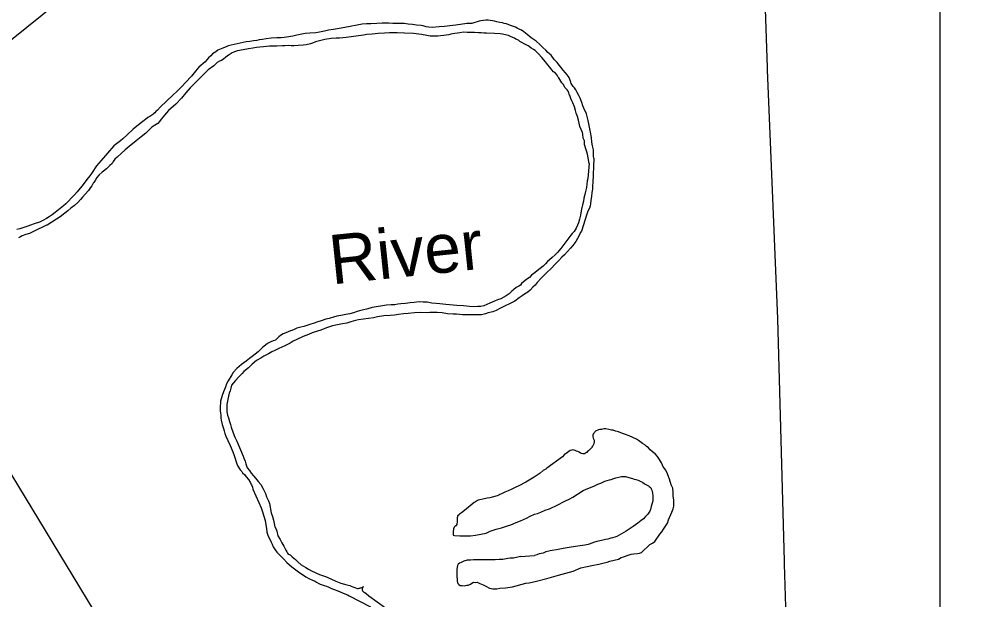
# Model space of a CAD drawing. Extents: x 1720274 to 1751788, y 372074 to 391887.
# Drawn here: x 1725183 to 1726800, y 387969 to 388953 of the extents above; entities that cross this region are included whole.
import ezdxf

# ---------------------------------------------------------------- set-up
doc = ezdxf.new("R2010")
doc.units = 0
for name, color, linetype in [('Level 10', 7, 'Continuous'), ('Level 2', 7, 'Continuous'), ('Level 9', 7, 'Continuous'), ('R_Draft', 7, 'Continuous')]:
    doc.layers.add(name, color=color, linetype=linetype)

msp = doc.modelspace()

# ---------------------------------------------------------------- linework, layer by layer
at = {"layer": 'Level 10'}
msp.add_lwpolyline([(1725245.1, 388978.7), (1725004.5, 388785.1)], dxfattribs=at)
at = {"layer": 'Level 2'}
msp.add_lwpolyline([(1726517.5, 386794.1), (1726507.7, 387180.9), (1726508, 387187.3), (1726491.7, 387614.2), (1726479.2, 388029.9), (1726479.1, 388035), (1726467.4, 388445.5), (1726450.4, 388867), (1726450.4, 388871.1), (1726443.9, 389052.9)], dxfattribs=at)
at = {"layer": 'Level 9'}
for points in [[(1726156, 388717.6), (1726155.7, 388721.1), (1726155.8, 388726.7), (1726155.5, 388731.7), (1726153.9, 388738.3), (1726152.7, 388744.8), (1726152, 388752.4), (1726150.4, 388761.5), (1726147.6, 388775.5), (1726146.3, 388781.5), (1726143.5, 388792.8), (1726139.3, 388802.4), (1726137.4, 388806.3), (1726135.8, 388811.9), (1726132.9, 388819.3), (1726130.7, 388823.6), (1726128, 388828.9), (1726125.5, 388833.1), (1726123.3, 388836.6), (1726121.2, 388839), (1726117.5, 388844.1), (1726117, 388846.3), (1726115, 388852.3), (1726114.2, 388854.3), (1726111, 388859), (1726108.1, 388862.4), (1726104.3, 388866.4), (1726094.1, 388879.4), (1726089.2, 388884.9), (1726083.6, 388892), (1726078.4, 388896.7), (1726075.1, 388900.3), (1726069.9, 388905.3), (1726064.7, 388910.1), (1726058.3, 388915.6), (1726050.1, 388921.5), (1726043.3, 388927.3), (1726037.4, 388931.7), (1726033.9, 388934.3), (1726029.7, 388936.2), (1726026.2, 388938), (1726023.3, 388939.3), (1726020.1, 388940.7), (1726016.7, 388942), (1726012.1, 388943.3), (1726008.3, 388944.9), (1726004.4, 388946), (1726001.3, 388946.7), (1725996.8, 388947.5), (1725991.6, 388948.8), (1725987.8, 388949.6), (1725984.3, 388950.3), (1725980.8, 388950.8), (1725977.1, 388951.1), (1725973.2, 388951.5), (1725969.2, 388950.9), (1725965, 388950.4), (1725961.9, 388949.7), (1725958.6, 388948.8), (1725954.4, 388947.4), (1725949.8, 388945.8), (1725946.5, 388945.7), (1725940.9, 388945.5), (1725930.3, 388944.2), (1725926.1, 388943.6), (1725922.5, 388942.9), (1725917.6, 388942.2), (1725912.4, 388941.6), (1725903.1, 388940.8), (1725894.2, 388940), (1725882.2, 388938.9), (1725877, 388939.3), (1725872.2, 388940), (1725867, 388941.5), (1725863.8, 388942.1), (1725855.6, 388942.8), (1725849.1, 388944), (1725841.9, 388944.7), (1725835.1, 388945.9), (1725816, 388945.7), (1725809.1, 388946.2), (1725803.2, 388946.3), (1725797.9, 388946.1), (1725788.6, 388945.5), (1725778.8, 388945.3), (1725771.4, 388945.2), (1725763.8, 388944.5), (1725755.2, 388943), (1725743.8, 388940.4), (1725734.5, 388939.1), (1725725.1, 388937.4), (1725715.3, 388935.8), (1725706.6, 388934.3), (1725700, 388932.8), (1725691.5, 388930.8), (1725685.6, 388930.1), (1725675, 388929.1), (1725667.1, 388928.8), (1725659, 388927.2), (1725653.3, 388925.7), (1725646.6, 388924.4)], [(1725646.6, 388924.4), (1725639.5, 388923.2), (1725631.5, 388922), (1725626.8, 388921.7), (1725619.1, 388921.4), (1725609.8, 388920.6), (1725601.5, 388919.7), (1725595.3, 388918.6), (1725589.4, 388917.8), (1725585.3, 388917.1), (1725579.6, 388916.2), (1725573.5, 388915.3), (1725567.7, 388914.5), (1725537, 388907.8), (1725534.7, 388906.6), (1725528.1, 388903.9), (1725524.9, 388902.7), (1725519.6, 388900.4), (1725516, 388897.9), (1725513.1, 388896.1), (1725510.5, 388894.4), (1725507.4, 388891.1), (1725503.6, 388887.5), (1725497.8, 388881), (1725487.5, 388871.6), (1725481.5, 388864.8), (1725474.8, 388856.6), (1725464.7, 388845.9), (1725459.3, 388839.5), (1725450.4, 388831.1), (1725443.2, 388824.2), (1725422.6, 388804.5), (1725417.5, 388799.1), (1725414.6, 388796.4), (1725412.6, 388794.4), (1725410.5, 388792.6), (1725409.2, 388791.7), (1725406.2, 388789.4), (1725404.3, 388788.2), (1725401.2, 388786.2), (1725397.7, 388783.4), (1725394.8, 388781.3), (1725388, 388776.3), (1725376, 388766.7), (1725365.6, 388756.7), (1725358.5, 388750.3), (1725354.4, 388746.8), (1725343.6, 388738.2), (1725322.1, 388713.6), (1725313.8, 388704.8), (1725306.8, 388693.5), (1725302.6, 388687.6), (1725297.6, 388681.4), (1725293, 388675.3), (1725289.1, 388669.9), (1725281.1, 388660.3), (1725277, 388655.2), (1725271.6, 388650.1), (1725266, 388644.1), (1725262, 388640.3), (1725258.3, 388637), (1725244.3, 388625.6), (1725239.1, 388621.7), (1725233.9, 388618), (1725229.2, 388615.3), (1725223.3, 388612.1), (1725217.6, 388609.2), (1725208.2, 388606.1), (1725202.1, 388604), (1725197.5, 388602.2), (1725189.2, 388599.6), (1725184, 388598), (1725179, 388596.9)], [(1726148.1, 388708.8), (1726146.3, 388718.3), (1726145.2, 388724.2), (1726140.5, 388740.9), (1726140.3, 388746.8), (1726138.3, 388751.6), (1726137.6, 388758.1), (1726136.7, 388761.2), (1726132.3, 388771.2), (1726131.1, 388777.1), (1726130, 388782.1), (1726128.4, 388788.2), (1726126.3, 388793.7), (1726124.9, 388798.4), (1726123.1, 388804.4), (1726120.8, 388811.3), (1726118.8, 388814.7), (1726117.3, 388818.8), (1726116, 388822.2), (1726114.3, 388826.1), (1726113.6, 388828.5), (1726112.8, 388831), (1726110.9, 388833.6), (1726107.4, 388836.8), (1726104, 388843.1), (1726102, 388845.1), (1726097, 388853.5), (1726096, 388854.7), (1726094, 388858.1), (1726091.4, 388861.7), (1726087.7, 388864.1), (1726084.9, 388867.2), (1726083.1, 388869.3), (1726081.1, 388872.1), (1726078.4, 388875.8), (1726076.1, 388878.4), (1726074.2, 388880.6), (1726068.1, 388888.2), (1726062.3, 388894.5), (1726056.5, 388900), (1726053.9, 388901.7), (1726050.2, 388904.2), (1726046.9, 388906.8), (1726044.8, 388908), (1726038.1, 388911.4), (1726034.3, 388913.4), (1726030.7, 388915.5), (1726028.3, 388917.3), (1726024.3, 388919.2), (1726022, 388920.6), (1726019.1, 388922.1), (1726015.1, 388923.9), (1726011.8, 388925.2), (1726008.6, 388926), (1726001.4, 388927.4), (1725997.3, 388928.2), (1725988, 388929), (1725974.5, 388929.2), (1725970.1, 388929.4), (1725965.5, 388929.8), (1725960.9, 388930), (1725954.1, 388930.3), (1725946.4, 388930.5), (1725941.4, 388930.6), (1725935.2, 388930.8), (1725929.2, 388929.9), (1725925.5, 388929.5), (1725920.7, 388929), (1725916.8, 388928.1), (1725913.8, 388927.4), (1725910.4, 388926.8), (1725905.8, 388926), (1725902.2, 388925.4), (1725896.6, 388924.6), (1725892.2, 388924), (1725887.8, 388924.1), (1725884.4, 388924), (1725879.2, 388924.3), (1725873.5, 388925.4), (1725864.1, 388927.3), (1725850.8, 388928.6), (1725835.7, 388929.4), (1725822.9, 388930), (1725810.1, 388929.7), (1725801.9, 388929.6), (1725790.7, 388928.6), (1725780.6, 388927.6), (1725771.8, 388926.9), (1725766, 388926.2), (1725736.8, 388922.1), (1725725.5, 388921.1), (1725719.8, 388920.9), (1725711.4, 388920.3), (1725700.8, 388918.4), (1725684.8, 388914.5), (1725679.7, 388912.5), (1725676.4, 388911.1), (1725669.2, 388909.4), (1725664.2, 388908.9), (1725655.3, 388908.2), (1725648.1, 388908.1)], [(1725648.1, 388908.1), (1725643.4, 388908.1), (1725638.8, 388908.3), (1725632.9, 388907.9), (1725628.8, 388907.8), (1725619.1, 388907.3), (1725613.1, 388907.4), (1725606.9, 388907.2), (1725597, 388906.3), (1725590.7, 388905.4), (1725585.1, 388904.9), (1725578.8, 388904.1), (1725571.1, 388902.6), (1725562.5, 388901.3), (1725552.7, 388899.3), (1725547.9, 388897.5), (1725543.7, 388896), (1725538.9, 388892.7), (1725536, 388890.8), (1725532.4, 388888.3), (1725529.4, 388886), (1725525.4, 388883.2), (1725522.4, 388881.8), (1725518.5, 388879.6), (1725516.4, 388878.1), (1725512.7, 388874.2), (1725503.2, 388867.2), (1725488.2, 388852.3), (1725472.5, 388836.8), (1725465.5, 388828.1), (1725457.7, 388819.2), (1725448.4, 388809.2), (1725435.7, 388798.3), (1725429.3, 388790.3), (1725423.6, 388783.6), (1725420.7, 388779.6), (1725417.8, 388776.5), (1725414.9, 388774.6), (1725407.6, 388770.1), (1725397.4, 388760.1), (1725389.5, 388753.8), (1725380.9, 388747.2), (1725369.4, 388737.3), (1725362.8, 388731.6), (1725355.9, 388725.3), (1725348.9, 388719.2), (1725345.2, 388715.8), (1725342.5, 388712.1), (1725340.4, 388708.8), (1725336.7, 388705), (1725330.7, 388699.6), (1725326.1, 388695.7), (1725323.8, 388693.8), (1725318.8, 388689.4), (1725314.3, 388684.7), (1725311.5, 388679.7), (1725309.4, 388676.4), (1725308.5, 388675), (1725306.3, 388670.6), (1725303.9, 388667.7), (1725300.2, 388663), (1725294.6, 388656.6), (1725290.3, 388651.7), (1725287, 388647.8), (1725282.3, 388642.6), (1725276.9, 388637.3), (1725270.6, 388632.7), (1725265.6, 388628.5), (1725260.5, 388624.4), (1725252.6, 388618.1), (1725246.3, 388614), (1725230.7, 388604), (1725229.4, 388603.8), (1725226, 388602.4), (1725220.3, 388599.7), (1725216.2, 388597.6), (1725211, 388595.1), (1725203, 388591), (1725200.7, 388590.1), (1725194.3, 388588), (1725188.2, 388586.2), (1725185.1, 388584.4), (1725181.9, 388582.5)], [(1726156, 388717.6), (1726154.4, 388675.6), (1726154.1, 388671.1), (1726153.6, 388665.2), (1726152.9, 388659.5), (1726152.2, 388652.8), (1726151.3, 388646.6), (1726150.4, 388640.1), (1726150, 388636.6), (1726148.6, 388632.6), (1726146.2, 388627.6), (1726144.2, 388622.9), (1726135.2, 388593.9), (1726133.2, 388590.9), (1726131.6, 388587.5), (1726128.7, 388581.4), (1726125.5, 388576.2), (1726120.7, 388569.4), (1726116.6, 388565), (1726106.2, 388554), (1726101.9, 388549.6), (1726096.6, 388544), (1726090.8, 388538), (1726083.9, 388530.6), (1726076.8, 388523.6), (1726071.8, 388519.4), (1726067.6, 388514.7), (1726060.1, 388507), (1726056.5, 388502.5), (1726052.8, 388499), (1726048.1, 388493.9), (1726044.1, 388490.8), (1726038.7, 388487.1), (1726035, 388484.5), (1726029.6, 388480.7), (1726022.5, 388475.5), (1725996.7, 388462.9), (1725990.7, 388459.6), (1725985.1, 388457), (1725977.4, 388455.3), (1725972.9, 388453.9), (1725965.7, 388452.4), (1725950, 388452.4), (1725933.8, 388451.9), (1725928.4, 388452.6), (1725923.5, 388453.1), (1725918, 388453.2), (1725908.6, 388454.1), (1725899.4, 388455.7), (1725891.1, 388455.9), (1725878.6, 388455.9), (1725873.7, 388455.8), (1725862.3, 388455.9), (1725852.7, 388455.7), (1725841.9, 388454.3), (1725833.8, 388453.7), (1725825.5, 388452.5), (1725818.8, 388451.8), (1725811, 388451), (1725800.6, 388450.5), (1725789.7, 388448.9), (1725782.8, 388447.3), (1725774.4, 388446), (1725757.8, 388443.8), (1725752.5, 388442.8), (1725744.6, 388440.3), (1725737.9, 388438.2), (1725730.6, 388436.8), (1725721.8, 388435), (1725713.6, 388433.4), (1725703.5, 388429.9), (1725694, 388426.3), (1725688.4, 388424.5), (1725679.2, 388421.4), (1725672.8, 388418.8), (1725663.7, 388415.5), (1725653.5, 388410.6), (1725647.1, 388407.3), (1725641.7, 388404.3), (1725633, 388399.9), (1725622.6, 388395.1), (1725615.8, 388391.7), (1725610.8, 388389.2), (1725605.5, 388386.3), (1725597.6, 388381.9), (1725592.2, 388378.8), (1725584.9, 388374.7), (1725577.7, 388368.8), (1725571.3, 388362.5), (1725563.7, 388356.4), (1725560.5, 388353), (1725555.1, 388347.3), (1725549.3, 388341.1), (1725545.9, 388336.8), (1725542.8, 388332.8), (1725541.5, 388327.7), (1725540.2, 388323.5), (1725538.9, 388319.2), (1725537.5, 388314.2), (1725536.4, 388309.1), (1725535.9, 388305.9)], [(1726148.1, 388708.8), (1726146.2, 388683.2), (1726145, 388678.9), (1726143.9, 388667.8), (1726142.1, 388660.9), (1726141, 388656), (1726139.3, 388649.7), (1726138.4, 388644.9), (1726137.2, 388638.7), (1726135.4, 388630.9), (1726134.1, 388625.1), (1726133.5, 388621.2), (1726132.1, 388614), (1726130.3, 388608.1), (1726128.5, 388604), (1726126.2, 388599.2), (1726122.7, 388593.4), (1726119.2, 388589.9), (1726117.4, 388587.3), (1726115.7, 388584.9), (1726100, 388564.7), (1726097.1, 388560.8), (1726095.2, 388558.4), (1726093.3, 388556.8), (1726090.4, 388553.8), (1726085.5, 388549.2), (1726081.1, 388545.1), (1726077.6, 388542.5), (1726074.4, 388538.7), (1726070.1, 388534.8), (1726065, 388530.6), (1726060.1, 388526.7), (1726056.9, 388523.9), (1726050.7, 388519.2), (1726047.4, 388515.6), (1726042.9, 388512.5), (1726033.8, 388505.2), (1726031.7, 388502.6), (1726029.1, 388500.9), (1726024.7, 388498.3), (1726020.3, 388494.5), (1726017.5, 388492.2), (1726012.8, 388488), (1726007.4, 388484.2), (1725998.4, 388479.3), (1725993.1, 388477.3), (1725987.8, 388475.2), (1725980.3, 388471.9), (1725974.9, 388469.5), (1725969.7, 388467.3), (1725964.7, 388466.5), (1725959.5, 388466), (1725951.6, 388465.8), (1725945.8, 388466.2), (1725935.2, 388467.3), (1725924.3, 388468.2), (1725905.3, 388469.8), (1725895.5, 388470.6), (1725889.1, 388471.2), (1725881.8, 388472), (1725873.9, 388473.4), (1725867.1, 388473.9), (1725860.1, 388474.2), (1725852, 388473), (1725845.1, 388472.4), (1725837.5, 388471.6), (1725829.3, 388471), (1725824.1, 388470), (1725819.1, 388469.2), (1725812.8, 388469), (1725804.9, 388468.7), (1725780.9, 388464.5), (1725777.5, 388463.4), (1725771.4, 388461.9), (1725766.2, 388460.8), (1725759.6, 388459), (1725755.1, 388457.6), (1725749.2, 388455.7), (1725742.9, 388454), (1725736, 388453), (1725727.6, 388451.3), (1725721, 388449.7), (1725715.5, 388448.4), (1725707.7, 388446.2), (1725702.2, 388444.6), (1725694.2, 388442.2), (1725688.9, 388440.2), (1725681.1, 388437.6), (1725677.1, 388436.2), (1725672.1, 388434.8), (1725664.9, 388432.6), (1725660.2, 388431.5), (1725653.2, 388429.6), (1725648.5, 388427.2), (1725644.9, 388425.8), (1725642.6, 388424.8), (1725638.4, 388423.1), (1725634.6, 388421.7), (1725629.8, 388419.8), (1725625.3, 388417.1), (1725622.9, 388414.9)], [(1725622.9, 388414.9), (1725620.4, 388412.5), (1725617.1, 388409.5), (1725613.3, 388408), (1725609.4, 388406.6), (1725606.8, 388405.2), (1725603.8, 388403.5), (1725600, 388401), (1725595.7, 388397.4), (1725592, 388394), (1725587.6, 388389.7), (1725577.7, 388381.5), (1725573.3, 388378), (1725567.3, 388373.7), (1725559.7, 388368.2), (1725551.8, 388361.1), (1725545.5, 388354.3), (1725543.3, 388350.5), (1725536.8, 388340.5), (1725533.7, 388334.1), (1725532.9, 388331.5), (1725530.7, 388325.6), (1725529.2, 388321.9), (1725526.8, 388315.4), (1725523.9, 388306), (1725523.7, 388303.1), (1725523.4, 388297.6), (1725523.4, 388293.6), (1725523.5, 388289.2), (1725523.8, 388285.9), (1725524.3, 388281.9), (1725524.7, 388277), (1725525.2, 388273.5), (1725526.8, 388266.5), (1725528.8, 388259.7), (1725530.3, 388255.6), (1725531.4, 388251.4), (1725533.2, 388246.5), (1725536.6, 388239.4), (1725540.5, 388230.8), (1725544.6, 388219.8), (1725547.2, 388213.7), (1725551.6, 388199.9), (1725553.5, 388195.8), (1725557, 388189.6), (1725560.3, 388186.7), (1725561.1, 388184.4), (1725565.2, 388181), (1725567.3, 388177.9), (1725571.6, 388173), (1725574.3, 388168.9), (1725575.5, 388166.1), (1725576.5, 388164.1), (1725578, 388160.3), (1725578.8, 388157), (1725589, 388134.5), (1725592.8, 388125.3), (1725595, 388118.4), (1725597.3, 388110.9), (1725599.5, 388103.5), (1725600.7, 388096.3), (1725601.7, 388090.3), (1725602.7, 388084), (1725604.1, 388079.1), (1725609.5, 388067.2), (1725611.2, 388063.5), (1725613.3, 388059.3), (1725616.6, 388054.1), (1725619.1, 388050.3), (1725624.5, 388045.2), (1725628.6, 388041), (1725631.2, 388038.4), (1725636.2, 388032.7), (1725644.7, 388025.4), (1725649.2, 388021.8), (1725655.9, 388016.6), (1725668.5, 388008.3), (1725674.9, 388004.8), (1725679.5, 388002.9), (1725683.1, 388001.3), (1725686.8, 387999.2), (1725690.6, 387996.9), (1725692.9, 387995.8), (1725699.7, 387993.4), (1725703.6, 387992.6), (1725707.2, 387990.8), (1725712.1, 387988.3), (1725716.7, 387986.9), (1725722.9, 387984.8), (1725726.8, 387982.7), (1725730.8, 387981.1), (1725734.4, 387979.7), (1725739.1, 387977.6), (1725742.1, 387976.3), (1725777.8, 387957.3)], [(1725535.9, 388305.9), (1725534.8, 388300.3), (1725534.9, 388293.7), (1725534.9, 388287.7), (1725535.8, 388282.1), (1725537.5, 388277.6), (1725539.1, 388271.6), (1725540.7, 388266.3), (1725542, 388262), (1725545.3, 388252.3), (1725548.2, 388244.8), (1725551.4, 388238.1), (1725562.4, 388212.8), (1725563.4, 388209.2), (1725565.5, 388204.5), (1725567.1, 388199.5), (1725569.4, 388192.7), (1725572.8, 388188.4), (1725576.1, 388184.2), (1725579.9, 388179.4), (1725583.5, 388175.3), (1725588, 388169.9), (1725592.2, 388164.6), (1725595.4, 388158.7), (1725598, 388153.9), (1725600, 388149.6), (1725602.1, 388143.9), (1725605.1, 388137.3), (1725607, 388132.6), (1725608, 388126.1), (1725608.5, 388122.7), (1725609.9, 388116.5), (1725612.2, 388110.3), (1725613.7, 388104.1), (1725614.8, 388098.6), (1725616.2, 388093.1), (1725618, 388089), (1725619.2, 388085.4), (1725621.2, 388077.9), (1725625, 388071.4), (1725627.9, 388065.8), (1725631.1, 388060), (1725634.8, 388053.5), (1725636.4, 388050.5), (1725637.6, 388048.5), (1725638.5, 388046.9), (1725642, 388045.3), (1725645.6, 388042.4), (1725650.8, 388037.8), (1725654.8, 388033.5), (1725660.8, 388028.9), (1725668.3, 388024.1), (1725673.1, 388021.1), (1725677.9, 388018.4), (1725691.5, 388012.5), (1725701.6, 388009), (1725710.6, 388004.7), (1725719.5, 388000.9), (1725727.9, 387997.4), (1725733.9, 387995.7), (1725737.7, 387994.5), (1725742.8, 387993.4), (1725745.2, 387992.5), (1725747.9, 387991.4), (1725749.8, 387990.9), (1725751.3, 387990.2), (1725754.2, 387989.3), (1725756.1, 387988.6), (1725757.3, 387988.7), (1725757.8, 387988.7), (1725758.9, 387988.9), (1725760, 387989.2), (1725760.8, 387989.4), (1725761.7, 387989.8), (1725763.4, 387990.3), (1725764.2, 387990.8), (1725765, 387991.1), (1725765.9, 387991.5), (1725765.8, 387991.5), (1725765.2, 387990.7), (1725764.6, 387989.8), (1725764.3, 387989.5), (1725764, 387987.9), (1725763.9, 387987.4), (1725764.1, 387986.2), (1725764.6, 387984.8), (1725765.4, 387983.5), (1725766.5, 387982.5), (1725768.6, 387981.9), (1725770.9, 387979.9), (1725775.1, 387976.2), (1725803.4, 387955.9)], [(1726255.3, 388220.1), (1726251.7, 388223.3), (1726248.6, 388226.6), (1726244.8, 388229.8), (1726242.6, 388231.9), (1726238.7, 388234.3), (1726231.9, 388239.3), (1726228.2, 388241.6), (1726222.3, 388244.4), (1726216, 388247.1), (1726209.8, 388249.2), (1726206.4, 388250.7), (1726202.1, 388252.3), (1726198, 388253.8), (1726192.6, 388255), (1726189, 388256.5), (1726186.3, 388257), (1726181.6, 388258), (1726176.5, 388258.8), (1726172.9, 388258.8), (1726169.3, 388258.1), (1726166.4, 388257.7), (1726163.8, 388257.1), (1726159.1, 388255.2), (1726157.6, 388254), (1726157, 388253.1), (1726155.6, 388251.4), (1726154.6, 388248.2), (1726154.7, 388245.2), (1726155.1, 388243.2), (1726156.6, 388239.7), (1726156.8, 388237.4), (1726156, 388233.5), (1726154.7, 388230.5), (1726154.1, 388229.5), (1726152.9, 388227.9), (1726152.1, 388226.9), (1726148.5, 388223.5), (1726147.1, 388222), (1726145.6, 388220.5), (1726144, 388219.2), (1726143.3, 388218.9), (1726142.2, 388218), (1726140.3, 388216.9), (1726139.6, 388216.5), (1726137.5, 388216.6), (1726135.1, 388217), (1726133.5, 388217.8), (1726131.2, 388219.4), (1726128.8, 388220.6), (1726126.9, 388221.3), (1726124.5, 388222.1), (1726122.8, 388222.8), (1726120.6, 388223.2), (1726118.8, 388223.1), (1726116.3, 388222.1), (1726113.8, 388220.8), (1726111.4, 388219.2), (1726105.7, 388214.9), (1726103.1, 388211.8), (1726076.4, 388192.6), (1726074.6, 388190.8), (1726070.6, 388188.3), (1726065.5, 388183.8), (1726055, 388177.2), (1726040.8, 388168.6), (1726029, 388162.2), (1726022.8, 388159.5), (1726016.4, 388156.4), (1726011.3, 388153.9), (1726005.7, 388151.5), (1725999.6, 388148.9), (1725997, 388147.5), (1725995, 388146.5), (1725992.3, 388145.6), (1725986.2, 388143.8), (1725980.1, 388142.4), (1725975.4, 388141.4), (1725968.3, 388139.9), (1725962.9, 388138.6), (1725960.4, 388138.1), (1725959.3, 388137.6), (1725957.4, 388136.4), (1725956, 388135.4), (1725953.7, 388134.1), (1725937.3, 388120.8), (1725932, 388116.7), (1725928.6, 388114.2), (1725927.9, 388113.4), (1725925.4, 388111.6), (1725925.1, 388111.1), (1725925.1, 388110.3), (1725925, 388109.7), (1725924.9, 388108.1), (1725924.5, 388105.9), (1725924.6, 388103.5), (1725924.8, 388103), (1725924.7, 388100.8), (1725924.4, 388098.4), (1725924.2, 388097.1), (1725922.7, 388094.9)], [(1726032.2, 388042.8), (1726027.6, 388041.8), (1726020, 388039.9), (1726014.5, 388039.8), (1726010.7, 388039.2), (1726002.1, 388037.5), (1725995.9, 388037.5), (1725988.8, 388037.3), (1725981.4, 388037), (1725974.8, 388037.1), (1725966.2, 388037.3), (1725952.5, 388037.2), (1725947.2, 388036.8), (1725941.5, 388036.5), (1725935.9, 388034.7), (1725931.5, 388032.7), (1725928.4, 388031.2), (1725926.4, 388029.7), (1725925.2, 388027.4), (1725924.2, 388021.4), (1725924, 388017.4), (1725924.3, 388008.4), (1725924.6, 388004.2), (1725924.8, 388001.1), (1725926.1, 387997.2), (1725927.7, 387995.3), (1725930, 387993.8), (1725933.3, 387993.4), (1725936.6, 387993.1), (1725941.3, 387994.3), (1725943.2, 387994.4), (1725944.3, 387994.6), (1725946.3, 387995.1), (1725947.1, 387996.1), (1725951, 387998.8), (1725951.7, 387998.8), (1725953, 387999), (1725955.7, 387998.8), (1725959, 387999), (1725959.5, 387998.7), (1725963, 387996.9), (1725968.8, 387994.6), (1725973.1, 387992.4), (1725979.5, 387989.2), (1725985.1, 387988), (1725992, 387988.1), (1725996.9, 387988.9), (1726006.5, 387989.8), (1726018.4, 387991.1), (1726041, 387997.3), (1726046.8, 387998.4), (1726058.8, 388000.9), (1726076.4, 388005.2), (1726096.1, 388011.1), (1726121.1, 388018.1), (1726134.3, 388023.4), (1726145, 388025.7), (1726153, 388027.7), (1726164.6, 388029.8), (1726171.5, 388031.2), (1726178.6, 388033.4), (1726183.3, 388034.9), (1726198, 388038.5), (1726202.5, 388040.9), (1726206.4, 388042.4), (1726214.2, 388045.2), (1726219.5, 388046.8), (1726224.1, 388047.5), (1726229.8, 388048.1), (1726233.5, 388048.4), (1726236.7, 388049.3), (1726251.2, 388062.9), (1726255.2, 388065.1), (1726259.5, 388068.4), (1726268.1, 388080.3), (1726271.1, 388084.8), (1726274.3, 388088.9), (1726277.3, 388094.4), (1726280.6, 388099.4), (1726282.5, 388105.1), (1726288.2, 388117.7), (1726290.4, 388123.3), (1726291.3, 388128.1), (1726291.7, 388134.9), (1726291.4, 388138.9), (1726290.6, 388145.2), (1726290.6, 388150.9), (1726290, 388158.7), (1726287.3, 388164.3), (1726284.4, 388173.7), (1726282.6, 388178.2), (1726279.6, 388185.7), (1726277.7, 388189.8), (1726274.8, 388193.3), (1726273.1, 388195.7), (1726271.8, 388199.1), (1726270.7, 388201.3), (1726267.1, 388207), (1726264.2, 388212.3), (1726259.8, 388216.5), (1726255.3, 388220.1)], [(1725922.7, 388094.9), (1725920.5, 388093.4), (1725919.6, 388092.2), (1725918.6, 388089.6), (1725918.3, 388088.4), (1725918.1, 388085.5), (1725918, 388084.6), (1725917.7, 388082.5), (1725917.9, 388081.5), (1725917.9, 388080.8), (1725917.8, 388080.7), (1725917.7, 388079.5), (1725917.7, 388079), (1725918, 388078.7), (1725920.4, 388078.3), (1725929.5, 388078), (1725938.7, 388077.5), (1725947.4, 388077.6), (1725956, 388078.7), (1725973.6, 388082.1), (1725980.4, 388085.6), (1725991, 388089), (1725999.8, 388091.3), (1726009.8, 388094.7), (1726015.3, 388096.4), (1726024.8, 388100.1), (1726032.2, 388103.3), (1726042.3, 388107.9), (1726048.2, 388111.3), (1726055.4, 388114.4), (1726060.8, 388115.8), (1726066.1, 388118.1), (1726073.5, 388121.2), (1726081.3, 388123.5), (1726095.4, 388130), (1726098.7, 388132), (1726102.7, 388134.2), (1726108, 388137.2), (1726114.5, 388139.9), (1726120.5, 388143), (1726138.2, 388154.3), (1726146.1, 388157.8), (1726156.4, 388161.9), (1726162.7, 388165.1), (1726168.2, 388167.2), (1726174.6, 388170.3), (1726182.5, 388172.6), (1726185.7, 388173.3), (1726189.9, 388174.7), (1726193.6, 388176.1), (1726203.2, 388178.3), (1726205.8, 388178.3), (1726207.7, 388178.3), (1726209.8, 388178.1), (1726215.4, 388176.8), (1726221.6, 388174.8), (1726224.3, 388173.9), (1726227.3, 388173.1), (1726231.2, 388172), (1726233.2, 388171.2), (1726235.8, 388169.9), (1726238.5, 388168.5), (1726242.1, 388166.1), (1726244.3, 388164.8), (1726246.6, 388163.4), (1726248.7, 388162.4), (1726250, 388161.5), (1726251.4, 388160.2), (1726252.4, 388158.9), (1726253.3, 388157.1), (1726254.4, 388155), (1726255, 388152.9), (1726255.2, 388149.9), (1726255.9, 388145.8), (1726256.1, 388142.5), (1726255.8, 388136.9), (1726254.6, 388131.5), (1726253.3, 388127.3), (1726252.2, 388122.5), (1726250.9, 388119.5), (1726247.3, 388114.3), (1726245.3, 388112), (1726243.2, 388109.7), (1726240, 388106.3), (1726236.4, 388103.5), (1726230.4, 388099.2), (1726222.7, 388093.4), (1726215.8, 388089), (1726210.8, 388085.5), (1726195, 388076.8), (1726191.8, 388075.6), (1726187.5, 388074.2), (1726185, 388073.9), (1726179.9, 388072.2), (1726176.1, 388071.7), (1726168.9, 388069.6), (1726161.4, 388068.1), (1726155.8, 388066.5), (1726154.4, 388066.1), (1726146.3, 388062.8), (1726140.8, 388061.7)], [(1726140.8, 388061.7), (1726125.1, 388059.6), (1726114.1, 388058), (1726104, 388056.1), (1726093, 388054.1), (1726085.7, 388053.1), (1726082.4, 388052.2), (1726080.2, 388051.5), (1726074.7, 388050.4), (1726070.2, 388048.6), (1726063.5, 388047.1), (1726059.7, 388045.6), (1726055.5, 388044.2)], [(1726032.2, 388042.8), (1726055.5, 388044.2)]]:
    msp.add_lwpolyline(points, dxfattribs=at)
at = {"layer": 'R_Draft'}
msp.add_line((1724881.2, 388657.5), (1727375.4, 384541.3), dxfattribs=at)
msp.add_lwpolyline([(1720610.3, 391249.6), (1726741.8, 391249.6), (1726741.8, 384893.1), (1720610.3, 384893.1)], close=True, dxfattribs=at)

# ---------------------------------------------------------------- texts
at = {"layer": 'Level 9'}
msp.add_text('River', height=83.42, rotation=6, dxfattribs=at).set_placement((1725712.6, 388503.5))

doc.saveas('drawing.dxf')
